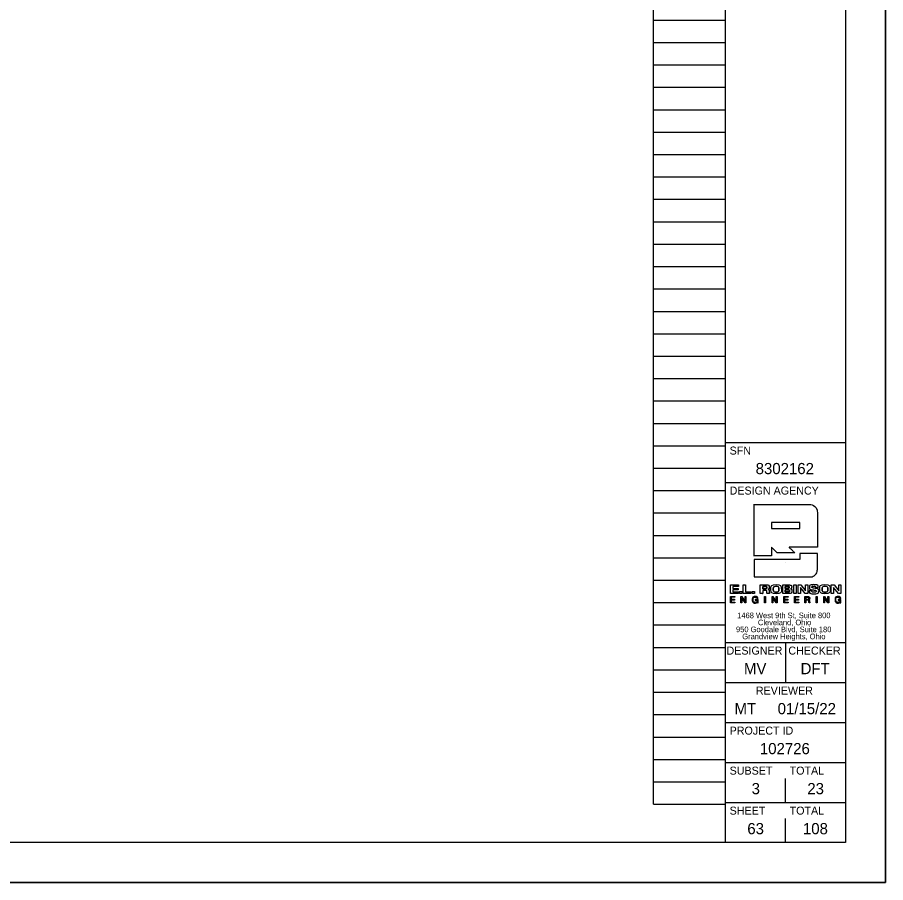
# Model space of a CAD drawing. Extents: x 0 to 34, y 0 to 22.
# Drawn here: x 23.15 to 34, y 0 to 10.81 of the extents above; entities that cross this region are included whole.
import ezdxf

# ---------------------------------------------------------------- set-up
doc = ezdxf.new("R2010")
doc.units = 0
for name, color, linetype in [('SC_Scratch1', 7, 'Continuous'), ('SH_Border', 7, 'Continuous'), ('SH_Cut_Line', 7, 'Continuous'), ('SH_Data', 7, 'Continuous')]:
    doc.layers.add(name, color=color, linetype=linetype)

msp = doc.modelspace()

# ---------------------------------------------------------------- linework, layer by layer
at = {"layer": 'SC_Scratch1'}
for p, q in [((31.1, 0.98), (31.1, 21.14)), ((32, 0.98), (32, 21.14)), ((31.1, 10.78), (32, 10.78)), ((31.1, 10.5), (32, 10.5)), ((31.1, 10.22), (32, 10.22)), ((31.1, 9.94), (32, 9.94)), ((31.1, 9.66), (32, 9.66)), ((31.1, 9.38), (32, 9.38)), ((31.1, 9.1), (32, 9.1)), ((31.1, 8.82), (32, 8.82)), ((31.1, 8.54), (32, 8.54)), ((31.1, 8.26), (32, 8.26)), ((31.1, 7.98), (32, 7.98)), ((31.1, 7.7), (32, 7.7)), ((31.1, 7.42), (32, 7.42)), ((31.1, 7.14), (32, 7.14)), ((31.1, 6.86), (32, 6.86)), ((31.1, 6.58), (32, 6.58)), ((31.1, 6.3), (32, 6.3)), ((31.1, 6.02), (32, 6.02)), ((31.1, 5.74), (32, 5.74)), ((31.1, 5.46), (32, 5.46)), ((31.1, 5.18), (32, 5.18)), ((31.1, 4.9), (32, 4.9)), ((31.1, 4.62), (32, 4.62)), ((31.1, 4.34), (32, 4.34)), ((31.1, 4.06), (32, 4.06)), ((31.1, 3.78), (32, 3.78)), ((31.1, 3.5), (32, 3.5)), ((31.1, 3.22), (32, 3.22)), ((31.1, 2.94), (32, 2.94)), ((31.1, 2.66), (32, 2.66)), ((31.1, 2.38), (32, 2.38)), ((31.1, 2.1), (32, 2.1)), ((31.1, 1.82), (32, 1.82)), ((31.1, 1.54), (32, 1.54)), ((31.1, 1.26), (32, 1.26)), ((31.1, 0.98), (32, 0.98))]:
    msp.add_line(p, q, dxfattribs=at)
msp.add_lwpolyline([(0, 22), (34, 22), (34, 0), (0, 0)], close=True, dxfattribs=at)
at = {"layer": 'SH_Border'}
for p, q in [((32, 0.5), (32, 21.5)), ((32, 5.5), (33.5, 5.5)), ((32, 5), (33.5, 5)), ((32, 3), (33.5, 3)), ((32.75, 3), (32.75, 2.5)), ((32, 2.5), (33.5, 2.5)), ((32, 2), (33.5, 2)), ((32, 1.5), (33.5, 1.5)), ((32, 1), (33.5, 1))]:
    msp.add_line(p, q, dxfattribs=at)
msp.add_lwpolyline([(1.5, 21.5), (33.5, 21.5), (33.5, 0.5), (1.5, 0.5)], close=True, dxfattribs=at)
at = {"layer": 'SH_Cut_Line'}
msp.add_lwpolyline([(0, 0), (34, 0), (34, 22), (0, 22)], close=True, dxfattribs=at)
at = {"layer": 'SH_Data'}
for p, q in [((32.929, 4.503), (32.574, 4.503)), ((32.574, 4.503), (32.574, 4.425)), ((32.929, 4.425), (32.929, 4.503)), ((32.574, 4.425), (32.929, 4.425)), ((32.75, 4), (32.75, 4)), ((32.463, 3.701), (32.463, 3.673)), ((32.743, 3.702), (32.743, 3.678)), ((32.743, 3.659), (32.743, 3.633)), ((33.001, 3.566), (33.001, 3.539)), ((33.001, 3.539), (33.023, 3.539)), ((32.75, 1), (32.75, 1.3)), ((32.75, 0.5), (32.75, 0.8)), ((32.375, 0.675), (32.375, 0.675))]:
    msp.add_line(p, q, dxfattribs=at)
for points in [[(32.06, 3.721), (32.161, 3.721), (32.161, 3.701), (32.089, 3.701), (32.089, 3.678), (32.158, 3.678), (32.158, 3.658), (32.089, 3.658), (32.089, 3.633), (32.162, 3.633), (32.162, 3.613), (32.06, 3.613), (32.06, 3.721)], [(32.22, 3.721), (32.249, 3.721), (32.249, 3.634), (32.316, 3.634), (32.316, 3.613), (32.22, 3.613), (32.22, 3.721)], [(32.851, 3.721), (32.881, 3.721), (32.881, 3.613), (32.851, 3.613), (32.851, 3.721)], [(32.999, 3.721), (33.027, 3.721), (33.027, 3.613), (32.995, 3.613), (32.936, 3.689), (32.936, 3.689), (32.936, 3.613), (32.907, 3.613), (32.907, 3.721), (32.941, 3.721), (32.999, 3.646), (32.999, 3.646), (32.999, 3.721)], [(33.413, 3.721), (33.442, 3.721), (33.442, 3.613), (33.41, 3.613), (33.35, 3.689), (33.35, 3.689), (33.35, 3.613), (33.321, 3.613), (33.321, 3.721), (33.356, 3.721), (33.413, 3.646), (33.413, 3.646), (33.413, 3.721)], [(32.175, 3.639), (32.205, 3.639), (32.205, 3.613), (32.175, 3.613), (32.175, 3.639)], [(32.331, 3.639), (32.361, 3.639), (32.361, 3.613), (32.331, 3.613), (32.331, 3.639)], [(32.059, 3.575), (32.114, 3.575), (32.114, 3.566), (32.07, 3.566), (32.07, 3.541), (32.111, 3.541), (32.111, 3.532), (32.07, 3.532), (32.07, 3.505), (32.114, 3.505), (32.114, 3.496), (32.059, 3.496), (32.059, 3.575)], [(32.191, 3.575), (32.203, 3.575), (32.244, 3.511), (32.244, 3.511), (32.244, 3.575), (32.254, 3.575), (32.254, 3.496), (32.243, 3.496), (32.202, 3.559), (32.201, 3.559), (32.201, 3.496), (32.191, 3.496), (32.191, 3.575)], [(32.487, 3.575), (32.498, 3.575), (32.498, 3.496), (32.487, 3.496), (32.487, 3.575)], [(32.581, 3.575), (32.592, 3.575), (32.633, 3.511), (32.633, 3.511), (32.633, 3.575), (32.643, 3.575), (32.643, 3.496), (32.632, 3.496), (32.591, 3.559), (32.591, 3.559), (32.591, 3.496), (32.581, 3.496), (32.581, 3.575)], [(32.726, 3.575), (32.781, 3.575), (32.781, 3.566), (32.737, 3.566), (32.737, 3.541), (32.778, 3.541), (32.778, 3.532), (32.737, 3.532), (32.737, 3.505), (32.781, 3.505), (32.781, 3.496), (32.726, 3.496), (32.726, 3.575)], [(32.859, 3.575), (32.913, 3.575), (32.913, 3.566), (32.869, 3.566), (32.869, 3.541), (32.91, 3.541), (32.91, 3.532), (32.869, 3.532), (32.869, 3.505), (32.913, 3.505), (32.913, 3.496), (32.859, 3.496), (32.859, 3.575)], [(33.133, 3.575), (33.143, 3.575), (33.143, 3.496), (33.133, 3.496), (33.133, 3.575)], [(33.226, 3.575), (33.237, 3.575), (33.279, 3.511), (33.279, 3.511), (33.279, 3.575), (33.289, 3.575), (33.289, 3.496), (33.277, 3.496), (33.236, 3.559), (33.236, 3.559), (33.236, 3.496), (33.226, 3.496), (33.226, 3.575)]]:
    msp.add_lwpolyline(points, dxfattribs=at)
for points, degree in [([(32.356, 4.083), (32.356, 4.086), (32.356, 4.724), (32.356, 4.727)], 2), ([(32.356, 4.727), (32.36, 4.727), (33.03, 4.727), (33.034, 4.727), (33.096, 4.727), (33.147, 4.677), (33.147, 4.614)], 3), ([(33.147, 4.614), (33.147, 4.612), (33.147, 4.194), (33.147, 4.192)], 2), ([(32.645, 4.121), (32.645, 4.121), (32.574, 4.191), (32.574, 4.192)], 2), ([(32.574, 4.192), (32.574, 4.191), (32.574, 4.083), (32.574, 4.083)], 2), ([(33.147, 4.192), (33.145, 4.192), (32.795, 4.192), (32.793, 4.192)], 2), ([(32.793, 4.192), (32.793, 4.191), (32.866, 4.121), (32.866, 4.121)], 2), ([(32.929, 4.115), (32.929, 4.115), (33.147, 4.115), (33.147, 4.115), (33.147, 4.115), (33.147, 3.933), (33.147, 3.933), (33.147, 3.87), (33.096, 3.82), (33.034, 3.82), (33.034, 3.82), (32.356, 3.82), (32.356, 3.82), (32.356, 3.82), (32.356, 4.037), (32.356, 4.037), (32.356, 4.037), (32.929, 4.037), (32.929, 4.037), (32.929, 4.037), (32.929, 4.115), (32.929, 4.115)], 3), ([(32.574, 4.083), (32.573, 4.083), (32.357, 4.083), (32.356, 4.083)], 2), ([(32.866, 4.121), (32.865, 4.121), (32.646, 4.121), (32.645, 4.121)], 2), ([(32.433, 3.613), (32.433, 3.613), (32.433, 3.721), (32.433, 3.721)], 2), ([(32.433, 3.721), (32.433, 3.721), (32.512, 3.721), (32.512, 3.721), (32.542, 3.721), (32.545, 3.703), (32.546, 3.692)], 3), ([(32.463, 3.673), (32.463, 3.673), (32.502, 3.673), (32.502, 3.673), (32.508, 3.673), (32.516, 3.677), (32.516, 3.687), (32.516, 3.698), (32.507, 3.701), (32.5, 3.701), (32.5, 3.701), (32.463, 3.701), (32.463, 3.701), (32.463, 3.701), (32.463, 3.673), (32.463, 3.673)], 3), ([(32.463, 3.673), (32.476, 3.673), (32.489, 3.673), (32.508, 3.673), (32.516, 3.677), (32.516, 3.698), (32.507, 3.701), (32.488, 3.701), (32.475, 3.701), (32.463, 3.701)], 3), ([(32.546, 3.692), (32.544, 3.679), (32.542, 3.67), (32.53, 3.666)], 2), ([(32.631, 3.61), (32.573, 3.61), (32.567, 3.645), (32.565, 3.667), (32.564, 3.69), (32.573, 3.724), (32.631, 3.724)], 3), ([(32.631, 3.63), (32.658, 3.63), (32.667, 3.65), (32.667, 3.667), (32.667, 3.684), (32.658, 3.704), (32.631, 3.704), (32.604, 3.704), (32.595, 3.684), (32.595, 3.667), (32.595, 3.65), (32.604, 3.63), (32.631, 3.63)], 3), ([(32.631, 3.704), (32.604, 3.704), (32.595, 3.684), (32.595, 3.667), (32.595, 3.65), (32.604, 3.63), (32.631, 3.63)], 3), ([(32.631, 3.724), (32.69, 3.724), (32.695, 3.689), (32.697, 3.667), (32.699, 3.644), (32.69, 3.61), (32.631, 3.61)], 3), ([(32.631, 3.63), (32.658, 3.63), (32.667, 3.65), (32.667, 3.667), (32.667, 3.684), (32.658, 3.704), (32.631, 3.704)], 3), ([(32.714, 3.613), (32.714, 3.613), (32.714, 3.721), (32.714, 3.721)], 2), ([(32.714, 3.721), (32.714, 3.721), (32.795, 3.721), (32.795, 3.721)], 2), ([(32.743, 3.678), (32.743, 3.678), (32.784, 3.678), (32.784, 3.678), (32.791, 3.678), (32.796, 3.682), (32.796, 3.69), (32.796, 3.697), (32.793, 3.702), (32.78, 3.702), (32.78, 3.702), (32.743, 3.702), (32.743, 3.702), (32.743, 3.702), (32.743, 3.678), (32.743, 3.678)], 3), ([(32.743, 3.678), (32.757, 3.678), (32.771, 3.678), (32.791, 3.681), (32.791, 3.683), (32.792, 3.697), (32.793, 3.702), (32.768, 3.702), (32.756, 3.702), (32.743, 3.702)], 3), ([(32.795, 3.721), (32.81, 3.718), (32.826, 3.714), (32.826, 3.694)], 2), ([(32.826, 3.694), (32.824, 3.686), (32.822, 3.675), (32.812, 3.672)], 2), ([(33.126, 3.69), (33.124, 3.704), (33.111, 3.706), (33.099, 3.706), (33.087, 3.706), (33.079, 3.7), (33.079, 3.693), (33.079, 3.687), (33.084, 3.684), (33.091, 3.683), (33.091, 3.683), (33.128, 3.677), (33.128, 3.677), (33.148, 3.673), (33.163, 3.666), (33.163, 3.646), (33.163, 3.626), (33.149, 3.61), (33.107, 3.61), (33.08, 3.61), (33.046, 3.613), (33.045, 3.647), (33.045, 3.647), (33.079, 3.647), (33.079, 3.647), (33.079, 3.632), (33.094, 3.629), (33.107, 3.629), (33.121, 3.629), (33.13, 3.634), (33.13, 3.643), (33.13, 3.651), (33.123, 3.654), (33.112, 3.655), (33.112, 3.655), (33.085, 3.66), (33.085, 3.66), (33.066, 3.662), (33.047, 3.668), (33.047, 3.69), (33.047, 3.715), (33.067, 3.724), (33.101, 3.724), (33.124, 3.724), (33.157, 3.721), (33.159, 3.69), (33.159, 3.69), (33.126, 3.69), (33.126, 3.69)], 3), ([(33.242, 3.61), (33.183, 3.61), (33.178, 3.645), (33.176, 3.667), (33.174, 3.69), (33.183, 3.724), (33.242, 3.724)], 3), ([(33.242, 3.63), (33.269, 3.63), (33.278, 3.65), (33.278, 3.667), (33.278, 3.684), (33.269, 3.704), (33.242, 3.704), (33.215, 3.704), (33.205, 3.684), (33.205, 3.667), (33.205, 3.65), (33.215, 3.63), (33.242, 3.63)], 3), ([(33.242, 3.704), (33.215, 3.704), (33.205, 3.684), (33.205, 3.667), (33.205, 3.65), (33.215, 3.63), (33.242, 3.63)], 3), ([(33.242, 3.724), (33.3, 3.724), (33.306, 3.689), (33.308, 3.667), (33.309, 3.644), (33.3, 3.61), (33.242, 3.61)], 3), ([(33.242, 3.63), (33.269, 3.63), (33.278, 3.65), (33.278, 3.667), (33.278, 3.684), (33.269, 3.704), (33.242, 3.704)], 3), ([(32.463, 3.613), (32.462, 3.613), (32.433, 3.613), (32.433, 3.613)], 2), ([(32.499, 3.653), (32.499, 3.653), (32.463, 3.653), (32.463, 3.653)], 2), ([(32.463, 3.653), (32.463, 3.652), (32.463, 3.613), (32.463, 3.613)], 2), ([(32.518, 3.613), (32.516, 3.618), (32.516, 3.622), (32.516, 3.634), (32.515, 3.649), (32.508, 3.65), (32.499, 3.653)], 3), ([(32.55, 3.613), (32.55, 3.613), (32.518, 3.613), (32.518, 3.613)], 2), ([(32.53, 3.666), (32.53, 3.666), (32.53, 3.665), (32.53, 3.665)], 2), ([(32.53, 3.665), (32.543, 3.663), (32.544, 3.647), (32.544, 3.636)], 2), ([(32.544, 3.636), (32.544, 3.631), (32.548, 3.619), (32.55, 3.613)], 2), ([(32.829, 3.645), (32.827, 3.632), (32.824, 3.613), (32.791, 3.613), (32.791, 3.613), (32.714, 3.613), (32.714, 3.613)], 3), ([(32.743, 3.633), (32.743, 3.633), (32.787, 3.633), (32.787, 3.633), (32.796, 3.633), (32.8, 3.639), (32.8, 3.646), (32.8, 3.655), (32.794, 3.659), (32.784, 3.659), (32.784, 3.659), (32.743, 3.659), (32.743, 3.659), (32.743, 3.659), (32.743, 3.633), (32.743, 3.633)], 3), ([(32.743, 3.633), (32.758, 3.633), (32.772, 3.633), (32.796, 3.633), (32.8, 3.639), (32.8, 3.655), (32.794, 3.659), (32.77, 3.659), (32.757, 3.659), (32.743, 3.659)], 3), ([(32.812, 3.672), (32.812, 3.672), (32.812, 3.672), (32.812, 3.672)], 2), ([(32.812, 3.672), (32.824, 3.67), (32.827, 3.656), (32.829, 3.645)], 2), ([(32.396, 3.506), (32.39, 3.498), (32.38, 3.494), (32.37, 3.494), (32.347, 3.494), (32.333, 3.514), (32.333, 3.534), (32.333, 3.557), (32.346, 3.577), (32.37, 3.577), (32.388, 3.577), (32.401, 3.569), (32.404, 3.551), (32.404, 3.551), (32.394, 3.551), (32.394, 3.551), (32.392, 3.562), (32.382, 3.568), (32.37, 3.568), (32.351, 3.568), (32.344, 3.551), (32.344, 3.534), (32.344, 3.518), (32.353, 3.503), (32.37, 3.503), (32.387, 3.503), (32.396, 3.515), (32.396, 3.529), (32.396, 3.529), (32.371, 3.529), (32.371, 3.529), (32.371, 3.529), (32.371, 3.538), (32.371, 3.538), (32.371, 3.538), (32.405, 3.538), (32.405, 3.538), (32.405, 3.538), (32.405, 3.496), (32.405, 3.496), (32.405, 3.496), (32.398, 3.496), (32.398, 3.496), (32.398, 3.496), (32.396, 3.506), (32.396, 3.506)], 3), ([(32.991, 3.575), (32.991, 3.575), (33.027, 3.575), (33.028, 3.575), (33.042, 3.575), (33.051, 3.567), (33.051, 3.554)], 3), ([(32.991, 3.496), (32.991, 3.497), (32.991, 3.574), (32.991, 3.575)], 2), ([(33.001, 3.496), (33.001, 3.496), (32.991, 3.496), (32.991, 3.496)], 2), ([(33.023, 3.539), (33.033, 3.539), (33.041, 3.541), (33.041, 3.552), (33.041, 3.56), (33.037, 3.566), (33.027, 3.566), (33.027, 3.566), (33.001, 3.566), (33.001, 3.566), (33.001, 3.566), (33.001, 3.539), (33.001, 3.539), (33.001, 3.539), (33.023, 3.539), (33.023, 3.539)], 3), ([(33.023, 3.539), (33.033, 3.539), (33.041, 3.541), (33.041, 3.56), (33.037, 3.566), (33.018, 3.566), (33.01, 3.566), (33.001, 3.566)], 3), ([(33.04, 3.516), (33.038, 3.523), (33.037, 3.53), (33.027, 3.53), (33.027, 3.53), (33.001, 3.53), (33.001, 3.53)], 3), ([(33.001, 3.53), (33.001, 3.53), (33.001, 3.496), (33.001, 3.496)], 2), ([(33.051, 3.554), (33.049, 3.545), (33.047, 3.537), (33.038, 3.534)], 2), ([(33.038, 3.534), (33.038, 3.534), (33.038, 3.534), (33.038, 3.534)], 2), ([(33.038, 3.534), (33.044, 3.529), (33.047, 3.525), (33.048, 3.518)], 2), ([(33.043, 3.496), (33.042, 3.5), (33.041, 3.508), (33.04, 3.516)], 2), ([(33.054, 3.496), (33.054, 3.496), (33.043, 3.496), (33.043, 3.496)], 2), ([(33.048, 3.518), (33.049, 3.51), (33.052, 3.502), (33.054, 3.496)], 2), ([(33.43, 3.506), (33.424, 3.498), (33.414, 3.494), (33.405, 3.494), (33.382, 3.494), (33.368, 3.514), (33.368, 3.534), (33.368, 3.557), (33.38, 3.577), (33.405, 3.577), (33.422, 3.577), (33.436, 3.569), (33.439, 3.551), (33.439, 3.551), (33.429, 3.551), (33.429, 3.551), (33.426, 3.562), (33.417, 3.568), (33.405, 3.568), (33.386, 3.568), (33.378, 3.551), (33.378, 3.534), (33.378, 3.518), (33.388, 3.503), (33.405, 3.503), (33.421, 3.503), (33.431, 3.515), (33.43, 3.529), (33.43, 3.529), (33.405, 3.529), (33.405, 3.529), (33.405, 3.529), (33.405, 3.538), (33.405, 3.538), (33.405, 3.538), (33.44, 3.538), (33.44, 3.538), (33.44, 3.538), (33.44, 3.496), (33.44, 3.496), (33.44, 3.496), (33.433, 3.496), (33.433, 3.496), (33.433, 3.496), (33.43, 3.506), (33.43, 3.506)], 3)]:
    msp.add_open_spline(points, degree=degree, dxfattribs=at)

# ---------------------------------------------------------------- texts
for s, height, p in [('SFN', 0.1, (32.05, 5.35)), ('8302162', 0.14, (32.375, 5.105)), ('DESIGN AGENCY', 0.1, (32.05, 4.85)), ('1468 West 9th St, Suite 800', 0.07, (32.145, 3.305)), ('Cleveland, Ohio', 0.07, (32.404, 3.217)), ('950 Goodale Blvd, Suite 180', 0.07, (32.13, 3.13)), ('Grandview Heights, Ohio', 0.07, (32.208, 3.042)), ('DESIGNER', 0.1, (32.011, 2.85)), ('CHECKER', 0.1, (32.784, 2.85)), ('MV', 0.14, (32.229, 2.605)), ('DFT', 0.14, (32.937, 2.605)), ('REVIEWER', 0.1, (32.378, 2.35)), ('MT', 0.14, (32.111, 2.105)), ('01/15/22', 0.14, (32.65, 2.105)), ('PROJECT ID', 0.1, (32.05, 1.85)), ('102726', 0.14, (32.428, 1.605)), ('SUBSET', 0.1, (32.05, 1.35)), ('TOTAL', 0.1, (32.8, 1.35)), ('3', 0.14, (32.325, 1.105)), ('23', 0.14, (33.021, 1.105)), ('SHEET', 0.1, (32.05, 0.85)), ('TOTAL', 0.1, (32.8, 0.85)), ('63', 0.14, (32.271, 0.605)), ('108', 0.14, (32.966, 0.605))]:
    msp.add_text(s, height=height, dxfattribs=at).set_placement(p)

doc.saveas('drawing.dxf')
